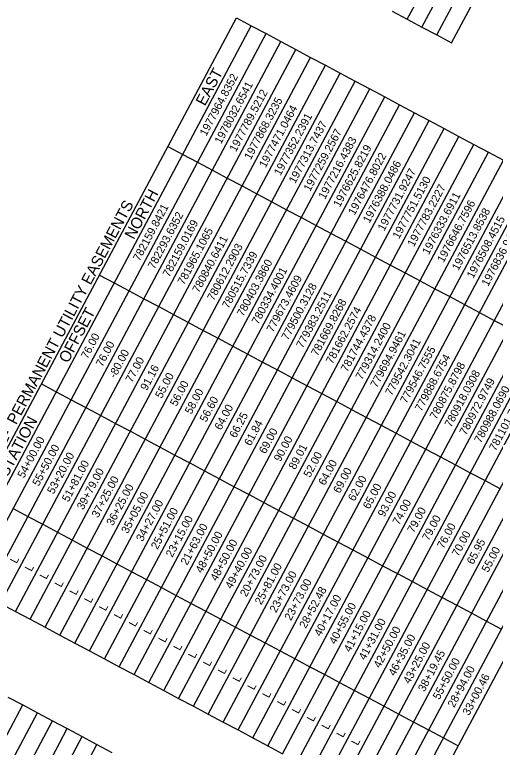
# Model space of a CAD drawing. Extents: x 1979034 to 1987549, y 771535 to 781988.
# Drawn here: x 1981883 to 1983234, y 777368 to 779426 of the extents above; entities that cross this region are included whole.
import ezdxf

# ---------------------------------------------------------------- set-up
doc = ezdxf.new("R2010")
doc.units = 0
for name, color, linetype in [('CTL Sheet Notes CELL', 7, 'Continuous'), ('CTL Sheet Table Cell', 7, 'Continuous'), ('CTL Sheet Text', 7, 'Continuous')]:
    doc.layers.add(name, color=color, linetype=linetype)

msp = doc.modelspace()

# ---------------------------------------------------------------- linework, layer by layer
at = {"layer": 'CTL Sheet Table Cell'}
for p, q in [((1982986.4, 779413.6), (1983816, 780970.4)), ((1983028.1, 779391.4), (1983857.7, 780948.2)), ((1983069.8, 779369.2), (1983899.4, 780925.9)), ((1983111.5, 779347), (1983941.1, 780903.7)), ((1982944.7, 779435.8), (1982986.4, 779413.6)), ((1981677, 777860.7), (1982506.6, 779417.5)), ((1982506.6, 779417.5), (1982548.3, 779395.2)), ((1982986.4, 779413.6), (1983028.1, 779391.4)), ((1981718.7, 777838.5), (1982548.3, 779395.2)), ((1982548.3, 779395.2), (1982590, 779373)), ((1983028.1, 779391.4), (1983069.8, 779369.2)), ((1981760.4, 777816.3), (1982590, 779373)), ((1982590, 779373), (1982631.7, 779350.8)), ((1983069.8, 779369.2), (1983111.5, 779347)), ((1981802.1, 777794), (1982631.7, 779350.8)), ((1982631.7, 779350.8), (1982673.4, 779328.6)), ((1981843.8, 777771.8), (1982673.4, 779328.6)), ((1982673.4, 779328.6), (1982715.1, 779306.3)), ((1981885.5, 777749.6), (1982715.1, 779306.3)), ((1982715.1, 779306.3), (1982756.8, 779284.1)), ((1981927.2, 777727.4), (1982756.8, 779284.1)), ((1982756.8, 779284.1), (1982798.5, 779261.9)), ((1981968.9, 777705.2), (1982798.5, 779261.9)), ((1982798.5, 779261.9), (1982840.2, 779239.7)), ((1982010.6, 777682.9), (1982840.2, 779239.7)), ((1982840.2, 779239.7), (1982881.9, 779217.5)), ((1982052.3, 777660.7), (1982881.9, 779217.5)), ((1982881.9, 779217.5), (1982923.6, 779195.2)), ((1982094, 777638.5), (1982923.6, 779195.2)), ((1982923.6, 779195.2), (1982965.3, 779173)), ((1982135.7, 777616.3), (1982965.3, 779173)), ((1982965.3, 779173), (1983007, 779150.8)), ((1982177.4, 777594), (1983007, 779150.8)), ((1983007, 779150.8), (1983048.7, 779128.6)), ((1982219.1, 777571.8), (1983048.7, 779128.6)), ((1983048.7, 779128.6), (1983090.4, 779106.4)), ((1982260.8, 777549.6), (1983090.4, 779106.4)), ((1983090.4, 779106.4), (1983132.1, 779084.1)), ((1982302.5, 777527.4), (1983132.1, 779084.1)), ((1983132.1, 779084.1), (1983173.8, 779061.9)), ((1982314, 779056.1), (1982355.7, 779033.8)), ((1982344.2, 777505.2), (1983173.8, 779061.9)), ((1983173.8, 779061.9), (1983215.5, 779039.7)), ((1982385.9, 777482.9), (1983215.5, 779039.7)), ((1983215.5, 779039.7), (1983257.2, 779017.5)), ((1982355.7, 779033.8), (1982397.4, 779011.6)), ((1982427.6, 777460.7), (1983257.2, 779017.5)), ((1982397.4, 779011.6), (1982439.1, 778989.4)), ((1982469.3, 777438.5), (1983298.9, 778995.3)), ((1982439.1, 778989.4), (1982480.8, 778967.2)), ((1982480.8, 778967.2), (1982522.5, 778945)), ((1982511, 777416.3), (1983340.6, 778973)), ((1982522.5, 778945), (1982564.2, 778922.7)), ((1982552.7, 777394.1), (1983382.3, 778950.8)), ((1982564.2, 778922.7), (1982605.9, 778900.5)), ((1982594.4, 777371.8), (1983424, 778928.6)), ((1982605.9, 778900.5), (1982647.6, 778878.3)), ((1982636.1, 777349.6), (1983465.7, 778906.4)), ((1982647.6, 778878.3), (1982689.3, 778856.1)), ((1982677.8, 777327.4), (1983507.4, 778884.1)), ((1982689.3, 778856.1), (1982731, 778833.9)), ((1982719.5, 777305.2), (1983549.1, 778861.9)), ((1982731, 778833.9), (1982772.7, 778811.6)), ((1982761.2, 777283), (1983590.8, 778839.7)), ((1982772.7, 778811.6), (1982814.4, 778789.4)), ((1982802.9, 777260.7), (1983632.5, 778817.5)), ((1982814.4, 778789.4), (1982856.1, 778767.2)), ((1982844.6, 777238.5), (1983674.2, 778795.3)), ((1982886.3, 777216.3), (1983715.9, 778773)), ((1982856.1, 778767.2), (1982897.8, 778745)), ((1982928, 777194.1), (1983757.6, 778750.8)), ((1982897.8, 778745), (1982939.5, 778722.7)), ((1982969.7, 777171.8), (1983799.3, 778728.6)), ((1982939.5, 778722.7), (1982981.2, 778700.5)), ((1983011.4, 777149.6), (1983841, 778706.4)), ((1982121.5, 778694.7), (1982163.2, 778672.5)), ((1982981.2, 778700.5), (1983022.9, 778678.3)), ((1982163.2, 778672.5), (1982204.9, 778650.2)), ((1983022.9, 778678.3), (1983064.6, 778656.1)), ((1982204.9, 778650.2), (1982246.5, 778628)), ((1983064.6, 778656.1), (1983106.3, 778633.9)), ((1982246.5, 778628), (1982288.2, 778605.8)), ((1983106.3, 778633.9), (1983148, 778611.6)), ((1982288.2, 778605.8), (1982329.9, 778583.6)), ((1983148, 778611.6), (1983189.7, 778589.4)), ((1982329.9, 778583.6), (1982371.6, 778561.3)), ((1983189.7, 778589.4), (1983231.4, 778567.2)), ((1983231.4, 778567.2), (1983273.1, 778545)), ((1982371.6, 778561.3), (1982413.3, 778539.1)), ((1982413.3, 778539.1), (1982455, 778516.9)), ((1982455, 778516.9), (1982496.7, 778494.7)), ((1982496.7, 778494.7), (1982538.4, 778472.5)), ((1982538.4, 778472.5), (1982580.1, 778450.2)), ((1982580.1, 778450.2), (1982621.8, 778428)), ((1982621.8, 778428), (1982663.5, 778405.8)), ((1982663.5, 778405.8), (1982705.2, 778383.6)), ((1981958.5, 778388.9), (1982000.2, 778366.7)), ((1982705.2, 778383.6), (1982746.9, 778361.4)), ((1982000.2, 778366.7), (1982041.9, 778344.4)), ((1982746.9, 778361.4), (1982788.6, 778339.1)), ((1982041.9, 778344.4), (1982083.6, 778322.2)), ((1982788.6, 778339.1), (1982830.3, 778316.9)), ((1982083.6, 778322.2), (1982125.3, 778300)), ((1982830.3, 778316.9), (1982872, 778294.7)), ((1982125.3, 778300), (1982167, 778277.8)), ((1982872, 778294.7), (1982913.7, 778272.5)), ((1982167, 778277.8), (1982208.7, 778255.6)), ((1982208.7, 778255.6), (1982250.4, 778233.3)), ((1982913.7, 778272.5), (1982955.4, 778250.3)), ((1982250.4, 778233.3), (1982292.1, 778211.1)), ((1982955.4, 778250.3), (1982997.1, 778228)), ((1982997.1, 778228), (1983038.8, 778205.8)), ((1982292.1, 778211.1), (1982333.8, 778188.9)), ((1983038.8, 778205.8), (1983080.5, 778183.6)), ((1982333.8, 778188.9), (1982375.5, 778166.7)), ((1983080.5, 778183.6), (1983122.2, 778161.4)), ((1982375.5, 778166.7), (1982417.2, 778144.5)), ((1983122.2, 778161.4), (1983163.9, 778139.2)), ((1982417.2, 778144.5), (1982458.9, 778122.2)), ((1983163.9, 778139.2), (1983205.6, 778116.9)), ((1982458.9, 778122.2), (1982500.6, 778100)), ((1983205.6, 778116.9), (1983247.3, 778094.7)), ((1982500.6, 778100), (1982542.3, 778077.8)), ((1982542.3, 778077.8), (1982584, 778055.6)), ((1982584, 778055.6), (1982625.7, 778033.3)), ((1981878.9, 778038.7), (1981920.6, 778016.4)), ((1982625.7, 778033.3), (1982667.4, 778011.1)), ((1981920.6, 778016.4), (1981962.3, 777994.2)), ((1982667.4, 778011.1), (1982709.1, 777988.9)), ((1981962.3, 777994.2), (1982004, 777972)), ((1982709.1, 777988.9), (1982750.8, 777966.7)), ((1982004, 777972), (1982045.7, 777949.8)), ((1982750.8, 777966.7), (1982792.5, 777944.5)), ((1982045.7, 777949.8), (1982087.4, 777927.5)), ((1982792.5, 777944.5), (1982834.2, 777922.2)), ((1982087.4, 777927.5), (1982129.1, 777905.3)), ((1982129.1, 777905.3), (1982170.8, 777883.1)), ((1982834.2, 777922.2), (1982875.9, 777900)), ((1982170.8, 777883.1), (1982212.5, 777860.9)), ((1982875.9, 777900), (1982917.6, 777877.8)), ((1982917.6, 777877.8), (1982959.3, 777855.6)), ((1982212.5, 777860.9), (1982254.2, 777838.7)), ((1982959.3, 777855.6), (1983001, 777833.4)), ((1982254.2, 777838.7), (1982295.9, 777816.4)), ((1983001, 777833.4), (1983042.7, 777811.1)), ((1982295.9, 777816.4), (1982337.6, 777794.2)), ((1983042.7, 777811.1), (1983084.4, 777788.9)), ((1982337.6, 777794.2), (1982379.3, 777772)), ((1983084.4, 777788.9), (1983126.1, 777766.7)), ((1981843.8, 777771.8), (1981885.5, 777749.6)), ((1982379.3, 777772), (1982421, 777749.8)), ((1983126.1, 777766.7), (1983167.8, 777744.5)), ((1981885.5, 777749.6), (1981927.2, 777727.4)), ((1982421, 777749.8), (1982462.7, 777727.6)), ((1983167.8, 777744.5), (1983209.5, 777722.3)), ((1981927.2, 777727.4), (1981968.9, 777705.2)), ((1982462.7, 777727.6), (1982504.4, 777705.3)), ((1983209.5, 777722.3), (1983251.2, 777700)), ((1981968.9, 777705.2), (1982010.6, 777682.9)), ((1982504.4, 777705.3), (1982546.1, 777683.1)), ((1982010.6, 777682.9), (1982052.3, 777660.7)), ((1982546.1, 777683.1), (1982587.8, 777660.9)), ((1982052.3, 777660.7), (1982094, 777638.5)), ((1982587.8, 777660.9), (1982629.5, 777638.7)), ((1982094, 777638.5), (1982135.7, 777616.3)), ((1982629.5, 777638.7), (1982671.2, 777616.5)), ((1982135.7, 777616.3), (1982177.4, 777594)), ((1982671.2, 777616.5), (1982712.9, 777594.2)), ((1982712.9, 777594.2), (1982754.6, 777572)), ((1982177.4, 777594), (1982219.1, 777571.8)), ((1982219.1, 777571.8), (1982260.8, 777549.6)), ((1982754.6, 777572), (1982796.3, 777549.8)), ((1982260.8, 777549.6), (1982302.5, 777527.4)), ((1982796.3, 777549.8), (1982838, 777527.6)), ((1982302.5, 777527.4), (1982344.2, 777505.2)), ((1982838, 777527.6), (1982879.7, 777505.3)), ((1981864.4, 777509), (1981906.1, 777486.8)), ((1982344.2, 777505.2), (1982385.9, 777482.9)), ((1982879.7, 777505.3), (1982921.4, 777483.1)), ((1981076.5, 775930), (1981906.1, 777486.8)), ((1981906.1, 777486.8), (1981947.8, 777464.6)), ((1982385.9, 777482.9), (1982427.6, 777460.7)), ((1982921.4, 777483.1), (1982963.1, 777460.9)), ((1981118.2, 775907.8), (1981947.8, 777464.6)), ((1981947.8, 777464.6), (1981989.5, 777442.3)), ((1982427.6, 777460.7), (1982469.3, 777438.5)), ((1982963.1, 777460.9), (1983004.8, 777438.7)), ((1981159.9, 775885.6), (1981989.5, 777442.3)), ((1981989.5, 777442.3), (1982031.2, 777420.1)), ((1982469.3, 777438.5), (1982511, 777416.3)), ((1983004.8, 777438.7), (1983046.5, 777416.5)), ((1981201.6, 775863.4), (1982031.2, 777420.1)), ((1982031.2, 777420.1), (1982072.9, 777397.9)), ((1982511, 777416.3), (1982552.7, 777394.1)), ((1983046.5, 777416.5), (1983088.2, 777394.2)), ((1981243.3, 775841.1), (1982072.9, 777397.9)), ((1982072.9, 777397.9), (1982114.6, 777375.7)), ((1982552.7, 777394.1), (1982594.4, 777371.8)), ((1983088.2, 777394.2), (1983129.9, 777372)), ((1981285, 775818.9), (1982114.6, 777375.7)), ((1982114.6, 777375.7), (1982156.3, 777353.5)), ((1982594.4, 777371.8), (1982636.1, 777349.6))]:
    msp.add_line(p, q, dxfattribs=at)

# ---------------------------------------------------------------- texts
at = {"layer": 'CTL Sheet Notes CELL'}
for s, p in [('EAST', (1982418.1, 779167.7)), ('NORTH', (1982218.2, 778792.5)), ('-L-  PERMANENT UTILITY EASEMENTS', (1981852.2, 778206.1)), ('OFFSET', (1982033.1, 778445.1)), ('STATION', (1981862.8, 778125.5))]:
    msp.add_text(s, height=31.5, rotation=61.9471, dxfattribs=at).set_placement(p)
at = {"layer": 'CTL Sheet Text'}
for s, p in [('1977964.8352', (1982421.6, 779083.2)), ('1978032.6541', (1982463.3, 779061)), ('1977789.5212', (1982505, 779038.8)), ('1977868.3235', (1982546.7, 779016.6)), ('1977471.0464', (1982588.4, 778994.3)), ('1977352.2391', (1982630.1, 778972.1)), ('1977313.7437', (1982671.8, 778949.9)), ('1977259.2567', (1982713.5, 778927.7)), ('1977216.4383', (1982755.2, 778905.5)), ('1976625.8219', (1982796.9, 778883.2)), ('1976476.8022', (1982838.6, 778861)), ('1976388.0486', (1982880.3, 778838.8)), ('1977731.9247', (1982921.9, 778816.6)), ('1977751.5130', (1982963.6, 778794.3)), ('1977783.2227', (1983005.3, 778772.1)), ('1976333.6911', (1983047, 778749.9)), ('782159.8421', (1982234.2, 778731.7)), ('1976646.7596', (1983088.7, 778727.7)), ('782293.6352', (1982275.9, 778709.5)), ('1976513.8538', (1983130.4, 778705.5)), ('1976508.4515', (1983172.1, 778683.2)), ('782159.0169', (1982317.6, 778687.2)), ('1976836.9466', (1983213.8, 778661)), ('781965.1065', (1982359.3, 778665)), ('780840.6411', (1982401, 778642.8)), ('780612.2903', (1982442.7, 778620.6)), ('780515.7339', (1982484.4, 778598.4)), ('780403.3860', (1982526.1, 778576.1)), ('780334.4001', (1982567.8, 778553.9)), ('779673.4609', (1982609.5, 778531.7)), ('779500.3128', (1982651.2, 778509.5)), ('779383.2511', (1982692.9, 778487.2)), ('781669.8268', (1982734.6, 778465)), ('781662.2574', (1982776.3, 778442.8)), ('781744.4378', (1982818, 778420.6)), ('779314.2400', (1982859.7, 778398.4)), ('76.00', (1982088, 778457.2)), ('779694.9461', (1982901.4, 778376.1)), ('76.00', (1982129.7, 778435)), ('779542.3041', (1982943.1, 778353.9)), ('-80.00', (1982166.1, 778402.9)), ('779546.7555', (1982984.8, 778331.7)), ('77.00', (1982213.1, 778390.5)), ('779888.6754', (1983026.5, 778309.5)), ('91.16', (1982254.8, 778368.3)), ('780875.8798', (1983068.2, 778287.3)), ('55.00', (1982296.5, 778346.1)), ('780918.0308', (1983109.9, 778265)), ('56.00', (1982338.1, 778323.9)), ('780972.9749', (1983151.6, 778242.8)), ('780988.0690', (1983193.3, 778220.6)), ('58.00', (1982379.8, 778301.6)), ('781101.7199', (1983235, 778198.4)), ('56.60', (1982421.5, 778279.4)), ('64.00', (1982463.2, 778257.2)), ('66.25', (1982504.9, 778235)), ('61.84', (1982546.6, 778212.8)), ('69.00', (1982588.3, 778190.5)), ('54+00.00', (1981909.3, 778121.9)), ('90.00', (1982630, 778168.3)), ('55+50.00', (1981951, 778099.6)), ('89.01', (1982671.7, 778146.1)), ('53+20.00', (1981992.7, 778077.4)), ('52.00', (1982713.4, 778123.9)), ('51+81.00', (1982034.4, 778055.2)), ('64.00', (1982755.1, 778101.7)), ('39+79.00', (1982076.1, 778033)), ('69.00', (1982796.8, 778079.4)), ('62.00', (1982838.5, 778057.2)), ('37+25.00', (1982117.7, 778010.7)), ('36+25.00', (1982159.4, 777988.5)), ('65.00', (1982880.2, 778035)), ('35+05.00', (1982201.1, 777966.3)), ('93.00', (1982921.9, 778012.8)), ('34+27.00', (1982242.8, 777944.1)), ('74.00', (1982963.6, 777990.5)), ('25+51.00', (1982284.5, 777921.9)), ('79.00', (1983005.3, 777968.3)), ('23+15.00', (1982326.2, 777899.6)), ('79.00', (1983047, 777946.1)), ('21+63.00', (1982367.9, 777877.4)), ('76.00', (1983088.7, 777923.9)), ('48+50.00', (1982409.6, 777855.2)), ('70.00', (1983130.4, 777901.7)), ('48+50.00', (1982451.3, 777833)), ('65.95', (1983172.1, 777879.4)), ('49+40.00', (1982493, 777810.8)), ('55.00', (1983213.8, 777857.2)), ('20+73.00', (1982534.7, 777788.5)), ('L', (1981888.7, 777882.3)), ('25+81.00', (1982576.4, 777766.3)), ('L', (1981930.4, 777860)), ('23+73.00', (1982618.1, 777744.1)), ('L', (1981972.1, 777837.8)), ('L', (1982013.8, 777815.6)), ('23+73.00', (1982659.8, 777721.9)), ('L', (1982055.5, 777793.4)), ('28+52.48', (1982701.5, 777699.7)), ('L', (1982097.2, 777771.2)), ('40+17.00', (1982743.2, 777677.4)), ('L', (1982138.9, 777748.9)), ('40+55.00', (1982784.9, 777655.2)), ('L', (1982180.6, 777726.7)), ('41+15.00', (1982826.6, 777633)), ('L', (1982222.3, 777704.5)), ('41+31.00', (1982868.3, 777610.8)), ('L', (1982264, 777682.3)), ('42+50.00', (1982910, 777588.5)), ('46+35.00', (1982951.7, 777566.3)), ('L', (1982305.7, 777660.1)), ('43+25.00', (1982993.4, 777544.1)), ('L', (1982347.3, 777637.8)), ('38+19.45', (1983035.1, 777521.9)), ('L', (1982389, 777615.6)), ('55+50.00', (1983076.8, 777499.7)), ('L', (1982430.7, 777593.4)), ('28+94.00', (1983118.5, 777477.4)), ('L', (1982472.4, 777571.2)), ('33+00.46', (1983160.2, 777455.2)), ('L', (1982514.1, 777549)), ('L', (1982555.8, 777526.7)), ('L', (1982597.5, 777504.5)), ('L', (1982639.2, 777482.3)), ('L', (1982680.9, 777460.1)), ('L', (1982722.6, 777437.8)), ('L', (1982764.3, 777415.6)), ('L', (1982806, 777393.4)), ('L', (1982847.7, 777371.2))]:
    msp.add_text(s, height=22.5, rotation=61.9471, dxfattribs=at).set_placement(p)

doc.saveas('drawing.dxf')
